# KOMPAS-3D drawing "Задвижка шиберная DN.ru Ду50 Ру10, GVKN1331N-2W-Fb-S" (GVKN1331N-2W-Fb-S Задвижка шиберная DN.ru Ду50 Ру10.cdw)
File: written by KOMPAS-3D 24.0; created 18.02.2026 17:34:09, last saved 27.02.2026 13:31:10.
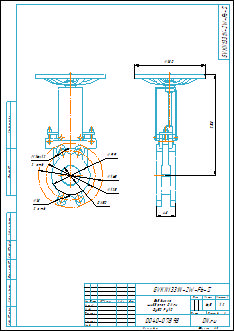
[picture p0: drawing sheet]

Document properties: art: D040-07898; Автор: R2D2; Форматы листов документа: A3; Полное имя файла: GVKN1331N-2W-Fb-S Задвижка шиберная DN.ru Ду50 Ру10.m3d; Масса: 6.5; Наименование: Задвижка шиберная DN.ru Ду50 Ру10; Количество листов документа: 1; Примечание: D040-07898

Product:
- Part/product: Задвижка шиберная DN.ru Ду50 Ру10  | designation GVKN1331N-2W-Fb-S
    Масса: 6.5
    Раздел спецификации: Прочие изделия
    Форматы листов документа: A3
    Примечание: D040-07898
    additional columns: D040-07898

Views: Вид 1, Спереди, Проекционный вид 2
Referenced files in E:\Работа\Зайцев\GVKN1331N-2W-Fb-S Задвижка шиберная DN.ru Ду50-300 Ру10\DN50\: GVKN1331N-2W-Fb-S Задвижка шиберная DN.ru Ду50 Ру10.m3d
Referenced files in E:\Работа\Зайцев\Для компаса\: чертеж DN.ru.cdt
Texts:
  GVKN1331N-2W-Fb-S
  чертеж DN.ru.cdt
  Задвижка
  шиберная DN.ru
  Ду50 Ру10
  prop
  Задвижка шиберная DN.ru Ду50 Ру10
  GVKN1331N-2W-Fb-S Задвижка шиберная DN.ru Ду50 Ру10
Dimensions and other numbers on the sheet: 0; 3; 2; 4; 16; 2 отв.; 18; 125; 99; 165; 50; 48; 258; 180; 1:2; 1; 6,5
